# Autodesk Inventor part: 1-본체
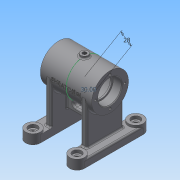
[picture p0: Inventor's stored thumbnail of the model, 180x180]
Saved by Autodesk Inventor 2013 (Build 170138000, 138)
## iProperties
Created: 2015-11
Part Number: 1-본체
Material: 일반
Document SubType Name: Modeling
Designer: user-11
Density: 1 g/cm^3
Author: user-11
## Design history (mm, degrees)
sketch "스케치1"
  geometry: C1 r 25 at (0, 0); 1 further point
  constraints: 1 centre point, 1 coincident
  dimensions: "d0" = 50 diameter of C1
extrude "돌출1" new body sketch "스케치1" stored distance "d2" = 70; taper "d3" = 0 deg
sketch "스케치2"
  geometry: C1 r 25 at (0, 0) reference; C2 r 16 at (0, 0)
  constraints: 1 centre point, 1 coincident
  dimensions: "d4" = 32 diameter of C2
extrude "돌출2" cut sketch "스케치2" distance "d6" = 12; taper "d7" = 0 deg
sketch "스케치3"
  geometry: C1 r 16 at (0, 0) reference; C2 r 14 at (0, 0)
  constraints: 1 centre point, 1 coincident
  dimensions: "d8" = 28 diameter of C2
extrude "돌출3" cut sketch "스케치3" distance "d10" = 2; taper "d11" = 0 deg
sketch "스케치4"
  geometry: C1 r 14 at (0, 0) reference; C2 r 21 at (0, 0)
  constraints: 1 centre point, 1 coincident
  dimensions: "d12" = 42 diameter of C2
extrude "돌출4" cut sketch "스케치4" distance "d14" = 21; taper "d15" = 0 deg
sketch "스케치5"
  geometry: C1 r 16 at (0, 0) reference; 1 further point
  constraints: 1 vertical alignment
  dimensions: "d16" = 20 distance of C1.centre point (0, 20)
hole "구멍1" sketch "스케치5" at (0, 20) diameter "d17" = 3.242; stored, may be unused: countersink angle "d21" = 90 deg, drill point angle "d23" = 118 deg; dims "d18" = 8, "d19" = 4, "d20" = 2, "d22" = 10
node "작업 평면1"
sketch "스케치6"
  geometry: L1 (-50, -20)-(50, -20); L2 (50, -20)-(50, -40); L3 (50, -40)-(-50, -40); L4 (-50, -40)-(-50, -20); C1 r 10 at (-40, -30); C2 r 10 at (40, -30); 2 further points
  constraints: 8 end point, 6 tangent, 2 centre point, 2 parallel, 1 horizontal, 1 midpoint, 1 perpendicular, 1 vertical alignment
  dimensions: "d33" = 20 distance of L1.end L2.end; "d35" = 40 distance of point (0, -40) point (0, 0); "d36" = 80 distance of C2.centre C1.centre
extrude "돌출5" join sketch "스케치6" distance "d37" = 10; taper "d38" = 0 deg
fillet "모깎기1" dims "d39" = 10
sketch "스케치7"
  geometry: C1 r 10 at (-40, 30); C2 r 10 at (40, 30); A1 r 10 centre (40, 30) between (40, 20) and (40, 40) reference; A2 r 10 centre (-40, 30) between (-40, 40) and (-40, 20) reference; 1 further point
  constraints: 2 centre point, 2 coincident, 1 equal radius
  dimensions: "d40" = 20 diameter of C1
extrude "돌출6" join sketch "스케치7" distance "d42" = 3; taper "d43" = 0 deg
sketch "스케치8"
  geometry: C1 r 10 at (0, 0) reference; C2 r 10 at (-80, 0) reference; C3 r 6 at (-80, 0); C4 r 6 at (0, 0); 1 further point
  constraints: 2 centre point, 2 coincident, 1 equal radius
  dimensions: "d44" = 12 diameter of C3
extrude "돌출7" cut sketch "스케치8" distance "d46" = 4; taper "d47" = 0 deg
sketch "스케치9"
  geometry: C1 r 3 at (-40, -30); C2 r 3 at (40, -30); A1 r 10 centre (40, -30) between (40, -40) and (40, -20) reference; A2 r 10 centre (-40, -30) between (-40, -20) and (-40, -40) reference; 1 further point
  constraints: 2 centre point, 2 coincident, 1 equal radius
  dimensions: "d48" = 6 diameter of C1
extrude "돌출8" cut sketch "스케치9" distance "d50" = 8; taper "d51" = 0 deg
sketch "스케치10"
  geometry: C1 r 6 at (0, 0) reference; C2 r 6 at (-80, 0) reference; C3 r 3.5 at (-80, 0); C4 r 3.5 at (0, 0); 1 further point
  constraints: 2 centre point, 2 coincident, 1 equal radius
  dimensions: "d52" = 7 diameter of C3
extrude "돌출9" cut sketch "스케치10" distance "d54" = 1; taper "d55" = -45 deg
fillet "모깎기2" dims "d56" = 0.3
sketch "스케치11"
  geometry: L1 (-40, 20)-(40, 20) reference; L2 (-25, 20)-(-25, 28); L3 (-25, 28)-(25, 28); L4 (25, 28)-(25, 20); L5 (-40, -40)-(40, -40) reference; L6 (40, -20)-(-40, -20) reference; L7 (25, 20)-(4, 20); L8 (4, -20)-(25, -20); L9 (4, 20)-(4, -20); L10 (25, -20)-(25, -28); L11 (25, -28)-(-25, -28); L12 (-25, -28)-(-25, -20); L13 (-25, -20)-(-4, -20); L14 (-4, -20)-(-4, 20); L15 (-4, 20)-(-25, 20); C1 r 3 at (40, -30) reference; C2 r 3 at (-40, -30) reference; A1 r 10 centre (40, -30) between (40, -40) and (40, -20) reference; A2 r 10 centre (-40, -30) between (-40, -20) and (-40, -40) reference; 3 further points
  constraints: 24 end point, 8 point on line, 5 perpendicular, 4 vertical alignment, 3 parallel, 2 midpoint, 1 collinear
  dimensions: "d57" = 8 distance between parallel lines of L3 L15; "d59" = 8 distance between parallel lines of L13 L11; "d60" = 8 distance between parallel lines of L9 L14; "d61" = 4 distance from line of L14 point (0, 0); "d62" = 50 distance of L10.end L11.end
extrude "돌출10" join sketch "스케치11" stored distance "d63" = 1; taper "d64" = 0 deg
sketch "스케치12"
  geometry: L1 (40, 0)-(40, 33.322) reference; L2 (12, 26.5)-(28, 26.5); L3 (28, 19.5)-(12, 19.5); L4 (53, -10)-(47, -10) reference; A1 r 3.5 centre (28, 23) between (28, 19.5) and (28, 26.5); A2 r 3.5 centre (12, 23) between (12, 26.5) and (12, 19.5); 2 further points
  constraints: 4 end point, 4 point on circle, 4 tangent, 2 centre point, 1 midpoint, 1 parallel, 1 perpendicular, 1 vertical alignment
  dimensions: "d65" = 23 dimension on A1 A2; "d67" = 3.5 radius of A1; "d68" = 33 distance from line of A1.centre L4
extrude "돌출11" cut sketch "스케치12" distance "d69" = 8; taper "d70" = 0 deg
node "작업 평면2"
sketch "스케치14"
  geometry: L1 (-4, -20)-(-4, 20) reference; L2 (4, 20)-(4, -20) reference; L3 (-4, 20)-(4, 20); L4 (4, 20)-(4, -20); L5 (4, -20)-(-4, -20); L6 (-4, -20)-(-4, 20); 1 further point
  constraints: 8 end point, 2 parallel, 1 horizontal, 1 perpendicular
extrude "돌출12" cut sketch "스케치14" distance "d77" = 20; taper "d78" = 0 deg
node "작업 평면3"
sketch "스케치15"
  geometry: C1 r 5 at (0, 0); 1 further point
  constraints: 1 centre point, 1 coincident
  dimensions: "d80" = 10 diameter of C1
extrude "돌출13" join sketch "스케치15" stored distance "d82" = 20; taper "d83" = 0 deg
sketch "스케치16"
  geometry: C1 r 5 at (0, 0) reference; 1 further point
  constraints: 1 coincident
hole "구멍2" sketch "스케치16" at (0, 0) diameter "d84" = 5.188; stored, may be unused: countersink angle "d88" = 90 deg, drill point angle "d90" = 118 deg; dims "d85" = 8, "d86" = 4, "d87" = 2, "d89" = 15
node "작업 평면4"
sketch "스케치17"
  geometry: L1 (0, 0)-(14, -24.249); L2 (0, 0)-(0, -25)
  constraints: 4 end point, 1 vertical, 1 vertical alignment, 1 other
  dimensions: "d92" = 28 distance of L1.start L1.end; "d93" = 30 deg angle of L1 L2
node "작업 평면5"
sketch "스케치18"
  geometry: C1 r 6 at (0, 0); 1 further point
  constraints: 1 centre point, 1 coincident
  dimensions: "d94" = 12 diameter of C1
extrude "돌출14" join sketch "스케치18" stored distance "d96" = 20; taper "d97" = 0 deg
sketch "스케치19"
  geometry: C1 r 6 at (0, 0) reference; 1 further point
  constraints: 1 coincident
hole "구멍3" sketch "스케치19" at (0, 0) diameter "d98" = 5.188; stored, may be unused: countersink angle "d102" = 90 deg, drill point angle "d104" = 118 deg; dims "d99" = 8, "d100" = 4, "d101" = 2, "d103" = 15
node "작업 평면6"
sketch "스케치20"
  geometry: 2 further points
  constraints: 1 coincident, 1 other
feature "엠보싱1" sketch "스케치20" dims "d105" = 0.5, "d106" = 0
fillet "모깎기3" dims "d107" = 0.3
chamfer "모따기1" distance "d108" = 1; stored, may be unused: second distance "d109" = 2, angle "d110" = 45 deg
fillet "모깎기4" dims "d111" = 2
fillet "모깎기5" dims "d112" = 2
fillet "모깎기6" dims "d113" = 2
fillet "모깎기7" dims "d114" = 2
fillet "모깎기8" dims "d115" = 2
fillet "모깎기9" dims "d116" = 2
fillet "모깎기10" dims "d117" = 2
fillet "모깎기11" dims "d118" = 2
node "솔리드1"
mirror "대칭1"
pattern_circular "원형 패턴1" dims angle "d25" = 360 deg
mirror "대칭2"
mirror "대칭3"
node "투영된 루프1"
node "투영된 루프2"
other parameters: "d27" = -68, "d76" = -45, "d79" = 28, "d91" = 0
